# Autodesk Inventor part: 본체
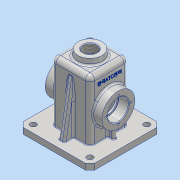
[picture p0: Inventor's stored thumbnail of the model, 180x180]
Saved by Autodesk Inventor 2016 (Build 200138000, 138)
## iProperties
Created: 2018-10
Part Number: 본체
Material: 알루미늄 6061
Document SubType Name: Modeling
Designer: user
Density: 2.7 g/cm^3
Appearance: 알루미늄 - 평지
Mass: 794.229 g
Surface Area: 899.5 cm^2
Volume: 294.159 cm^3
Author: user
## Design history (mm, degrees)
sketch "스케치1"
  geometry: L1 (-60, -60)-(60, -60); L2 (60, -60)-(60, 60); L3 (60, 60)-(-60, 60); L4 (-60, 60)-(-60, -60); L5 (-60, -60)-(60, 60); L6 (60, -60)-(-60, 60); 1 further point
  constraints: 12 end point, 2 midpoint, 2 parallel, 2 perpendicular, 1 horizontal
  dimensions: "d0" = 120 distance of L3.end L2.end
extrude "돌출1" new body sketch "스케치1" distance "d1" = 10; taper "d2" = 0 deg
sketch "스케치2"
  geometry: L1 (-32.5, -32.5)-(32.5, -32.5); L2 (32.5, -32.5)-(32.5, 32.5); L3 (32.5, 32.5)-(-32.5, 32.5); L4 (-32.5, 32.5)-(-32.5, -32.5); L5 (-32.5, -32.5)-(32.5, 32.5); L6 (32.5, -32.5)-(-32.5, 32.5); 1 further point
  constraints: 12 end point, 2 midpoint, 2 parallel, 2 perpendicular, 1 horizontal
  dimensions: "d3" = 65 distance of L3.end L2.end
extrude "돌출2" join sketch "스케치2" distance "d4" = 100; taper "d5" = 0 deg
feature "쉘1" dims "d6" = 10, "d7" = 5
node "작업 평면1"
sketch "스케치3"
  geometry: C1 r 20 at (0, 0); 1 further point
  constraints: 1 centre point, 1 coincident
  dimensions: "d9" = 40 diameter of C1
extrude "돌출3" join sketch "스케치3" stored distance "d10" = 100; taper "d11" = 7 deg
sketch "스케치4"
  geometry: L1 (10, -27.5)-(10, 92.5) reference; C1 r 27.5 at (-45, 32.5); 2 further points
  constraints: 1 centre point, 1 horizontal alignment, 1 midpoint
  dimensions: "d12" = 55 diameter of C1; "d13" = 55 distance from line of L1 C1.centre
extrude "돌출4" join sketch "스케치4" distance "d14" = 15; taper "d15" = 0 deg
sketch "스케치5"
  geometry: C1 r 27.5 at (0, 0) reference; 1 further point
hole "구멍1" sketch "스케치5" at (0, 0) diameter "d16" = 30; stored, may be unused: countersink angle "d20" = 90 deg, drill point angle "d22" = 0 deg; dims "d17" = 6, "d18" = 35, "d19" = 17, "d21" = 20
sketch "스케치6" dims "d23" = 42
  geometry: C1 r 17.5 at (0, 0) reference; C2 r 27.5 at (0, 0) reference; 3 further points
  constraints: 2 horizontal alignment, 1 coincident, 2 other
hole "구멍2" sketch "스케치6" at (-21, 0) diameter "d24" = 3.242; stored, may be unused: countersink angle "d28" = 90 deg, drill point angle "d30" = 118 deg; dims "d25" = 8, "d26" = 35, "d27" = 17, "d29" = 10
sketch "스케치7"
  geometry: L1 (-60, 0)-(-60, 10) reference; L2 (-60, 10)-(-32.5, 10) reference; L3 (-32.5, 10)-(-32.5, 110) reference; L4 (-32.5, 110)-(-21.228, 110) reference; L5 (-21.228, 110)-(-20, 120) reference; L6 (-20, 120)-(20, 120) reference; L7 (20, 120)-(21.228, 110) reference; L8 (21.228, 110)-(32.5, 110) reference; L9 (32.5, 110)-(32.5, 10) reference; L10 (32.5, 10)-(60, 10) reference; L11 (60, 10)-(60, 0) reference; L12 (60, 0)-(27.5, 0) reference; L13 (27.5, 0)-(27.5, 105) reference; L14 (27.5, 105)-(-27.5, 105) reference; L15 (-27.5, 105)-(-27.5, 0) reference; L16 (-27.5, 0)-(-60, 0) reference; L17 (48, 10)-(32.5, 97.905); 1 further point
  constraints: 2 end point, 2 point on line
  dimensions: "d34" = 12 distance from line of L11 L17.start; "d35" = 10 deg angle of L11 L17
extrude "돌출5" join sketch "스케치7" stored distance "d36" = 10; taper "d37" = 0 deg
sketch "스케치8"
  geometry: L1 (32.5, 32.5)-(32.5, -32.5) reference; L2 (32.5, 3)-(42.5, 3); L3 (42.5, 3)-(42.5, -3); L4 (42.5, -3)-(32.5, -3); L5 (32.5, -3)-(32.5, 3); L6 (27.5, -27.5)-(27.5, 27.5) reference; 2 further points
  constraints: 8 end point, 2 parallel, 1 horizontal, 1 horizontal alignment, 1 midpoint, 1 perpendicular, 1 point on line
  dimensions: "d38" = 15 distance between parallel lines of L6 L3; "d39" = 6 distance between parallel lines of L4 L2
extrude "돌출6" join sketch "스케치8" stored distance "d40" = 10; taper "d41" = 0 deg
sketch "스케치9"
  geometry: L1 (-47.5, -47.5)-(47.5, -47.5); L2 (47.5, -47.5)-(47.5, 47.5); L3 (47.5, 47.5)-(-47.5, 47.5); L4 (-47.5, 47.5)-(-47.5, -47.5); L5 (-47.5, -47.5)-(47.5, 47.5); L6 (47.5, -47.5)-(-47.5, 47.5); C1 r 5 at (47.5, 47.5); C2 r 5 at (-47.5, 47.5); C3 r 5 at (-47.5, -47.5); C4 r 5 at (47.5, -47.5); 1 further point
  constraints: 12 end point, 4 centre point, 4 coincident, 3 equal radius, 2 midpoint, 2 parallel, 2 perpendicular, 1 horizontal
  dimensions: "d42" = 95 distance of L3.end L2.end; "d43" = 10 diameter of C1
extrude "돌출7" cut sketch "스케치9" stored distance "d44" = 10; taper "d45" = 0 deg
chamfer "모따기1" distance "d46" = 8; stored, may be unused: second distance "d47" = 2, angle "d48" = 45 deg
sketch "스케치10"
  geometry: C1 r 20 at (0, 0) reference
hole "구멍3" sketch "스케치10" at (0, 0) diameter "d49" = 22.835; stored, may be unused: countersink angle "d53" = 90 deg, drill point angle "d55" = 0 deg; dims "d50" = 50, "d51" = 35, "d52" = 17, "d54" = 10
fillet "모깎기1" dims "d58" = 8
fillet "모깎기2" dims "d59" = 8
fillet "모깎기3" dims "d60" = 3
fillet "모깎기4" dims "d61" = 1
fillet "모깎기5" dims "d62" = 3
fillet "모깎기6" dims "d63" = 3
fillet "모깎기7" dims "d64" = 3
chamfer "모따기2" distance "d65" = 1; stored, may be unused: second distance "d66" = 2, angle "d67" = 45 deg
sketch "스케치11"
  geometry: L1 (0, -8)-(91, -8) reference; L2 (-18, 44.5)-(-18, 4.5) reference; L3 (92, 53.123)-(92, 84.5) reference; L4 (92, 84.5)-(102, 84.5) reference; L5 (102, 84.5)-(102, -35.5) reference; L6 (102, -35.5)-(92, -35.5) reference; L7 (92, -35.5)-(92, -4.123) reference; L8 (91, 0)-(65.166, 0) reference; L9 (76.904, 18.5)-(91, 18.5) reference; L10 (91, 0)-(91, 18.5) reference; L11 (91, 49)-(65.166, 49) reference; L12 (91, 30.5)-(91, 49) reference; L13 (91, 30.5)-(76.904, 30.5) reference; L14 (28.834, 0)-(0, 0) reference; L15 (0, 0)-(0, 49) reference; L16 (28.834, 49)-(0, 49) reference; C1 r 17.5 at (47, 24.5) reference; A1 r 30.5 centre (47, 24.5) between (65.166, 0) and (76.904, 18.5) reference; A2 r 30.5 centre (47, 24.5) between (76.904, 30.5) and (65.166, 49) reference; A3 r 30.5 centre (47, 24.5) between (28.834, 49) and (28.834, 0) reference; 2 further points
  constraints: 2 horizontal alignment, 3 other
  dimensions: "d71" = 32.5 distance from line of L1 point (8, 24.5); "d75" = 26 distance from line of L2 point (8, 24.5)
feature "엠보싱1" sketch "스케치11" dims "d0" = 120, "d8" = -120, "d73" = 0.5, "d74" = 0
fillet "모깎기8" dims "d76" = 0.3
node "솔리드1"
pattern_circular "원형 패턴1" dims angle "d32" = 360 deg
mirror "대칭1"
mirror "대칭2"
mirror "대칭3"
node "절단 모서리 투영1"
node "절단 모서리 투영2"
